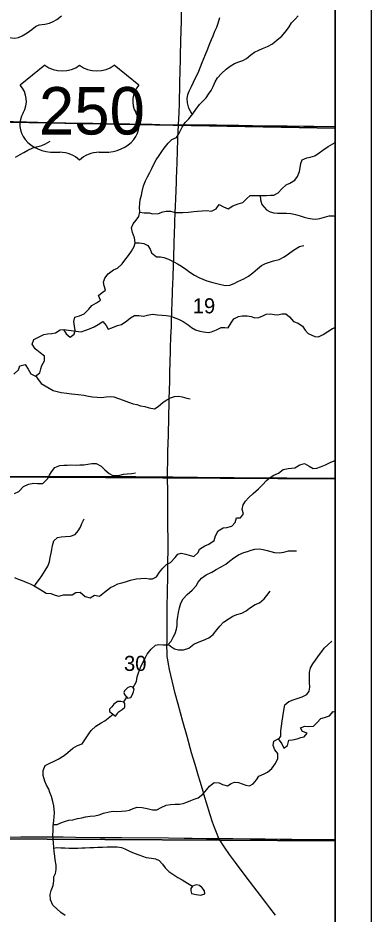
# Model space of a CAD drawing. Extents: x 0 to 34, y 0 to 22.
# Drawn here: x 19.16 to 20.14, y 14.964 to 17.453 of the extents above; entities that cross this region are included whole.
import ezdxf

# ---------------------------------------------------------------- set-up
doc = ezdxf.new("R2010")
doc.units = 0
for name, color, linetype in [('GM_X_County_Road', 7, 'Continuous'), ('GM_X_Minor_Lake', 7, 'Continuous'), ('GM_X_Minor_River', 7, 'Continuous'), ('GM_X_Rail_Line', 7, 'Continuous'), ('GM_X_Section_Text', 7, 'Continuous'), ('GM_X_State_Route', 7, 'Continuous'), ('GM_X_Township_Road', 7, 'Continuous'), ('GM_X_US_Route', 7, 'Continuous'), ('GM_X_US_Shield', 7, 'Continuous'), ('SH_Data', 7, 'Continuous')]:
    doc.layers.add(name, color=color, linetype=linetype)

msp = doc.modelspace()

# ---------------------------------------------------------------- linework, layer by layer
at = {"layer": 'GM_X_County_Road'}
msp.add_lwpolyline([(19.0861, 15.1755), (19.1151, 15.1769), (19.1368, 15.1775), (19.1679, 15.1781), (19.1866, 15.1784), (19.2239, 15.1785), (19.2425, 15.1784), (19.286, 15.1781), (19.3202, 15.1776), (19.3886, 15.1766), (19.4477, 15.1761), (19.5782, 15.1751), (19.6217, 15.1747), (19.6435, 15.1744), (19.6838, 15.1737), (19.718, 15.1739)], dxfattribs=at)
at = {"layer": 'GM_X_Minor_Lake'}
for points in [[(19.4645, 15.5631), (19.4732, 15.565), (19.4778, 15.5715), (19.4812, 15.581), (19.4827, 15.589), (19.4796, 15.5939), (19.4731, 15.5962), (19.4641, 15.5923), (19.4557, 15.5843), (19.4542, 15.579), (19.4558, 15.5733)], [(19.4558, 15.5733), (19.4645, 15.5631)], [(19.4313, 15.5137), (19.4366, 15.5213), (19.4388, 15.5251), (19.4494, 15.5316), (19.457, 15.5384), (19.4574, 15.5487), (19.4539, 15.5528), (19.4456, 15.5547), (19.4365, 15.5539), (19.4266, 15.5471), (19.4206, 15.5398), (19.4149, 15.5334), (19.4142, 15.5269)], [(19.4142, 15.5269), (19.4313, 15.5137)], [(19.6402, 15.0344), (19.6402, 15.0279), (19.6425, 15.0207), (19.6546, 15.0181), (19.6683, 15.0159), (19.6789, 15.0201), (19.6781, 15.0281), (19.6717, 15.0368), (19.664, 15.0428), (19.6561, 15.0447), (19.6493, 15.0435), (19.6451, 15.0412)], [(19.6451, 15.0412), (19.6402, 15.0344)]]:
    msp.add_lwpolyline(points, dxfattribs=at)
at = {"layer": 'GM_X_Minor_River'}
for points in [[(19.0144, 17.4536), (19.0243, 17.4433), (19.0379, 17.4404), (19.055, 17.4362), (19.0687, 17.4332), (19.082, 17.4276), (19.0953, 17.4204), (19.109, 17.4095), (19.12, 17.4046), (19.134, 17.3993), (19.1515, 17.3971), (19.1621, 17.3994), (19.172, 17.4036), (19.1863, 17.412), (19.1988, 17.4211), (19.2091, 17.4295), (19.2197, 17.4341), (19.2348, 17.4357), (19.2481, 17.4387), (19.2583, 17.4437), (19.2682, 17.449), (19.281, 17.4589)], [(19.287, 16.5882), (19.2943, 16.576), (19.3057, 16.5662), (19.3166, 16.5746), (19.3189, 16.5852), (19.3173, 16.5974), (19.3158, 16.6103), (19.318, 16.6224), (19.3313, 16.6259), (19.3445, 16.6316), (19.3574, 16.6441), (19.3653, 16.6544), (19.3786, 16.6617), (19.3892, 16.6689), (19.3835, 16.6818), (19.3937, 16.6909), (19.4035, 16.6967), (19.4001, 16.7092), (19.3982, 16.719), (19.4019, 16.73), (19.411, 16.7426), (19.4254, 16.7533), (19.4367, 16.7586), (19.45, 16.7704), (19.4598, 16.7841), (19.4674, 16.7936), (19.4753, 16.805), (19.4828, 16.8183), (19.4855, 16.8286), (19.4839, 16.8426), (19.4782, 16.857), (19.4751, 16.8703), (19.48, 16.8817), (19.4883, 16.8919), (19.4959, 16.9018), (19.4985, 16.9151), (19.4981, 16.9265), (19.4988, 16.9379), (19.4995, 16.9478), (19.5029, 16.961), (19.5055, 16.9709), (19.5085, 16.9865), (19.5145, 17.0009), (19.5202, 17.0116), (19.5262, 17.0241), (19.5319, 17.0347), (19.5379, 17.0473), (19.5443, 17.0594), (19.5526, 17.0712), (19.5594, 17.0819), (19.5662, 17.0914), (19.5772, 17.1055), (19.587, 17.1157), (19.6003, 17.1215), (19.6071, 17.1317), (19.6165, 17.1503), (19.6244, 17.1625), (19.6347, 17.1732), (19.646, 17.1872), (19.6543, 17.1994), (19.6645, 17.2127), (19.6736, 17.2222), (19.6823, 17.2317), (19.6895, 17.2413), (19.697, 17.2519), (19.7019, 17.2625), (19.7076, 17.2755), (19.714, 17.2865), (19.725, 17.2987), (19.7378, 17.3112), (19.7492, 17.3196), (19.7617, 17.3272), (19.7734, 17.3311), (19.7848, 17.3353), (19.7946, 17.3406), (19.8071, 17.3513), (19.817, 17.3581), (19.8287, 17.3642), (19.8389, 17.3688), (19.8533, 17.3738), (19.867, 17.3818), (19.8802, 17.3925), (19.8931, 17.4031), (19.9055, 17.4184), (19.9135, 17.4286), (19.9199, 17.4393), (19.9297, 17.4495), (19.9384, 17.4591)], [(19.6445, 17.1854), (19.6399, 17.1922), (19.6346, 17.2031), (19.6311, 17.2172), (19.6299, 17.2286), (19.6322, 17.2407), (19.6356, 17.2502), (19.6416, 17.2627), (19.6473, 17.2749), (19.6525, 17.2848), (19.6574, 17.2954), (19.662, 17.3053), (19.6669, 17.3175), (19.6721, 17.33), (19.6763, 17.341), (19.6812, 17.3516), (19.6872, 17.3672), (19.6913, 17.3779), (19.6974, 17.3931), (19.7019, 17.4037), (19.7068, 17.4162), (19.7121, 17.4276), (19.7162, 17.4386), (19.7203, 17.455)], [(19.154, 17.0662), (19.1661, 17.0735), (19.1767, 17.0796), (19.1877, 17.0864), (19.2021, 17.0922), (19.2123, 17.0952), (19.2263, 17.0991), (19.2369, 17.1033), (19.2502, 17.1113)], [(19.4982, 16.9137), (19.5106, 16.9117), (19.5243, 16.9122), (19.5349, 16.9092), (19.5501, 16.91), (19.5622, 16.9146), (19.5721, 16.9161), (19.5834, 16.9161), (19.5967, 16.9131), (19.6074, 16.9124), (19.6176, 16.9128), (19.6339, 16.9136), (19.6487, 16.916), (19.6589, 16.9167), (19.6718, 16.9175), (19.6836, 16.918), (19.6972, 16.9169), (19.7101, 16.923), (19.7192, 16.9351), (19.7306, 16.9287), (19.7439, 16.9231), (19.7571, 16.9318), (19.7715, 16.9368), (19.7848, 16.9407), (19.7943, 16.9509), (19.8045, 16.9597), (19.8151, 16.9601), (19.8504, 16.9602), (19.861, 16.9606), (19.8709, 16.9614), (19.883, 16.9671), (19.8932, 16.9789), (19.9049, 16.99), (19.9148, 16.9946), (19.9288, 17.0029), (19.9363, 17.0125), (19.9416, 17.0269), (19.9435, 17.0371), (19.9453, 17.0489), (19.9491, 17.0595), (19.962, 17.0649), (19.9718, 17.0661), (19.9843, 17.0707), (19.9968, 17.0783), (20.0067, 17.0859), (20.0218, 17.0958), (20.0339, 17.1038), (20.0404, 17.1077)], [(19.8325, 16.9602), (19.8333, 16.948), (19.8372, 16.9355), (19.8501, 16.92), (19.86, 16.9143), (19.8706, 16.9121), (19.8809, 16.911), (19.8949, 16.911), (19.9059, 16.9114), (19.918, 16.9103), (19.9306, 16.9073), (19.9439, 16.9036), (19.9549, 16.9002), (19.9655, 16.8968), (19.9769, 16.8953), (19.9867, 16.8942), (19.9985, 16.8962), (20.0114, 16.9), (20.0243, 16.9031), (20.036, 16.9031), (20.0404, 16.902)], [(19.4855, 16.8286), (19.4968, 16.8282), (19.5094, 16.8271), (19.5208, 16.8215), (19.5276, 16.8112), (19.5307, 16.8006), (19.5447, 16.79), (19.5558, 16.7893), (19.5652, 16.7875), (19.5782, 16.7829), (19.5926, 16.7762), (19.6036, 16.7705), (19.6146, 16.7637), (19.626, 16.7558), (19.6374, 16.7471), (19.6504, 16.7388), (19.6625, 16.7327), (19.6735, 16.7275), (19.6849, 16.7229), (19.7009, 16.7184), (19.7123, 16.7154), (19.7233, 16.7132), (19.7365, 16.7102), (19.7483, 16.7114), (19.7608, 16.7156), (19.771, 16.7209), (19.7877, 16.7286), (19.7998, 16.7358), (19.8123, 16.745), (19.8252, 16.7564), (19.8365, 16.7659), (19.8475, 16.7712), (19.8581, 16.7751), (19.8695, 16.7785), (19.885, 16.7824), (19.899, 16.7892), (19.9112, 16.7976), (19.9248, 16.8083), (19.9414, 16.8182), (19.954, 16.8209)], [(19.287, 16.5882), (19.336, 16.5815), (19.3458, 16.5849), (19.3591, 16.5895), (19.3723, 16.5949), (19.3833, 16.6021), (19.3958, 16.6101), (19.4053, 16.5991), (19.4103, 16.5885), (19.4209, 16.5927), (19.4364, 16.5992), (19.4478, 16.6012), (19.4622, 16.6115), (19.4724, 16.6206), (19.4834, 16.6263), (19.4955, 16.6264), (19.5088, 16.6249), (19.5232, 16.6283), (19.535, 16.6307), (19.5479, 16.6288), (19.5608, 16.6277), (19.5714, 16.6266), (19.5843, 16.6244), (19.5961, 16.6206), (19.606, 16.6161), (19.6192, 16.6104), (19.6329, 16.601), (19.6424, 16.5934), (19.6531, 16.587), (19.6656, 16.5829), (19.6755, 16.5814), (19.6884, 16.5799), (19.6979, 16.5811), (19.7111, 16.5864), (19.7244, 16.5929), (19.7342, 16.5929), (19.7437, 16.5926), (19.752, 16.6063), (19.7592, 16.6173), (19.7725, 16.6242), (19.7827, 16.6261), (19.7963, 16.6258), (19.8081, 16.6243), (19.8176, 16.6205), (19.8286, 16.6209), (19.8396, 16.6255), (19.8494, 16.6301), (19.8612, 16.6309), (19.8711, 16.6294), (19.8806, 16.6287), (19.8934, 16.631), (19.9037, 16.6314), (19.9143, 16.6227), (19.925, 16.6098), (19.9379, 16.6057), (19.9504, 16.5974), (19.9573, 16.586), (19.9661, 16.5762), (19.9843, 16.5683), (19.9945, 16.5676), (20.0078, 16.5737), (20.0207, 16.5824), (20.0335, 16.5901), (20.0404, 16.5933)], [(19.1489, 16.464), (19.1618, 16.4755), (19.1656, 16.4865), (19.18, 16.4907), (19.1883, 16.4778), (19.1963, 16.4646), (19.2089, 16.4582), (19.221, 16.4677), (19.224, 16.4783), (19.227, 16.4878), (19.2345, 16.5003), (19.2338, 16.5136), (19.222, 16.5227), (19.2079, 16.5337), (19.1999, 16.5469), (19.204, 16.5602), (19.2196, 16.5678), (19.2324, 16.5736), (19.2423, 16.5755), (19.2544, 16.5763), (19.2647, 16.5786), (19.2775, 16.5866), (19.287, 16.5882)], [(19.2099, 16.4589), (19.215, 16.4513), (19.2252, 16.4381), (19.2355, 16.4309), (19.2473, 16.4245), (19.2583, 16.4185), (19.2689, 16.4158), (19.2807, 16.4132), (19.2959, 16.411), (19.3092, 16.4095), (19.3274, 16.4073), (19.3433, 16.4054), (19.3562, 16.4025), (19.3676, 16.4006), (19.3801, 16.3995), (19.3919, 16.3991), (19.4048, 16.4003), (19.4173, 16.4015), (19.4268, 16.4008), (19.4397, 16.3959), (19.4522, 16.391), (19.467, 16.3857), (19.4803, 16.3812), (19.4906, 16.379), (19.5001, 16.376), (19.5122, 16.3737), (19.5247, 16.3703), (19.5392, 16.3673), (19.5498, 16.3742), (19.5634, 16.386), (19.5732, 16.3925), (19.5842, 16.3982), (19.5952, 16.4013), (19.6058, 16.4021), (19.6157, 16.4006), (19.629, 16.3972), (19.6385, 16.395)], [(19.1507, 16.1324), (19.1624, 16.1374), (19.176, 16.1519), (19.1893, 16.1583), (19.2041, 16.161), (19.2147, 16.1603), (19.2295, 16.16), (19.2423, 16.1725), (19.248, 16.1828), (19.2537, 16.1927), (19.2631, 16.2041), (19.2768, 16.2095), (19.2874, 16.2106), (19.2972, 16.211), (19.3075, 16.2114), (19.3219, 16.2111), (19.3325, 16.2115), (19.3435, 16.2119), (19.3545, 16.2135), (19.3651, 16.2158), (19.3773, 16.2155), (19.3909, 16.2079), (19.4016, 16.1977), (19.4134, 16.1875), (19.4236, 16.1822), (19.4335, 16.1819), (19.4434, 16.1834), (19.4532, 16.1857), (19.4634, 16.1869), (19.4767, 16.1881), (19.487, 16.1892)], [(19.151, 15.8991), (19.1608, 15.8946), (19.1719, 15.8908), (19.1848, 15.8851), (19.1943, 15.881), (19.2053, 15.8757), (19.2193, 15.8674), (19.2288, 15.8614), (19.2391, 15.8557), (19.2516, 15.8546), (19.2634, 15.8493), (19.274, 15.8467), (19.2869, 15.8509), (19.3002, 15.8502), (19.3112, 15.8506), (19.321, 15.8567), (19.3335, 15.8579), (19.3472, 15.8462), (19.3609, 15.8421), (19.3726, 15.8493), (19.3867, 15.8471), (19.4007, 15.8577), (19.417, 15.8714), (19.4276, 15.876), (19.4378, 15.881), (19.4484, 15.8841), (19.4586, 15.8871), (19.4723, 15.8913), (19.4882, 15.8948), (19.5015, 15.8964), (19.514, 15.8968), (19.5242, 15.8953), (19.5341, 15.8953), (19.5447, 15.9003), (19.5534, 15.914), (19.5621, 15.925), (19.5727, 15.9349), (19.584, 15.9406), (19.5965, 15.9539), (19.6041, 15.9635), (19.6136, 15.9665), (19.6261, 15.9639), (19.6382, 15.9598), (19.6489, 15.9575), (19.6606, 15.9682), (19.664, 15.9777), (19.6795, 15.9865), (19.6901, 15.9914), (19.7045, 16.0017), (19.7086, 16.0142), (19.7158, 16.0283), (19.7302, 16.0371), (19.7404, 16.0375), (19.7541, 16.0413), (19.7628, 16.0516), (19.7665, 16.0645), (19.7779, 16.0645), (19.7866, 16.0752), (19.7831, 16.0877), (19.7858, 16.101), (19.7918, 16.1105), (19.8001, 16.1204), (19.8134, 16.1322), (19.8281, 16.1447), (19.8395, 16.1565), (19.8504, 16.1687), (19.8606, 16.1767), (19.8705, 16.1828), (19.8834, 16.1889), (19.8966, 16.1985), (19.9103, 16.2019), (19.9285, 16.2035), (19.9429, 16.2119), (19.9561, 16.2153), (19.969, 16.2085), (19.9793, 16.2017), (19.9903, 16.2029), (20.0005, 16.2064), (20.0138, 16.2121), (20.0267, 16.2186), (20.038, 16.2228), (20.0404, 16.2236)], [(19.2065, 15.875), (19.211, 15.8818), (19.22, 15.894), (19.2268, 15.9035), (19.2363, 15.9179), (19.2431, 15.9301), (19.2476, 15.9419), (19.2494, 15.954), (19.2521, 15.9662), (19.2543, 15.9768), (19.2562, 15.9874), (19.2599, 16.0007), (19.2701, 16.0102), (19.28, 16.0118), (19.2925, 16.013), (19.3062, 16.0134), (19.319, 16.0184), (19.3277, 16.0282), (19.3338, 16.0389), (19.3375, 16.0488), (19.3439, 16.0617)], [(19.4799, 15.5933), (19.489, 15.6102), (19.4917, 15.6228), (19.495, 15.6342), (19.5003, 15.649), (19.506, 15.6608), (19.5135, 15.6748), (19.5192, 15.6855), (19.5297, 15.6995), (19.5419, 15.7106), (19.5517, 15.7129), (19.5627, 15.7118), (19.576, 15.7118), (19.5858, 15.7221), (19.5915, 15.7331), (19.5971, 15.7434), (19.6005, 15.7555), (19.602, 15.765), (19.6027, 15.7775), (19.6038, 15.7904), (19.6061, 15.8018), (19.6091, 15.8144), (19.6124, 15.8273), (19.6185, 15.8398), (19.6298, 15.8516), (19.6438, 15.8638), (19.6548, 15.8752), (19.6608, 15.8858), (19.6695, 15.8969), (19.6828, 15.9064), (19.6987, 15.914), (19.7108, 15.9213), (19.7244, 15.9282), (19.7373, 15.9362), (19.7475, 15.9445), (19.7593, 15.9533), (19.7725, 15.9621), (19.7873, 15.9678), (19.7979, 15.9713), (19.8074, 15.9747), (19.818, 15.9778), (19.8305, 15.9782), (19.8411, 15.9767), (19.8521, 15.9741), (19.8624, 15.9707), (19.8723, 15.9681), (19.8852, 15.967), (19.898, 15.9689), (19.9117, 15.9724), (19.9231, 15.9732), (19.9337, 15.9728)], [(19.5777, 15.7136), (19.5836, 15.708), (19.5946, 15.7005), (19.6064, 15.6975), (19.6197, 15.6979), (19.6344, 15.7029), (19.6481, 15.7132), (19.659, 15.7185), (19.6753, 15.7246), (19.6897, 15.7315), (19.7022, 15.7403), (19.7128, 15.7536), (19.7207, 15.7635), (19.7309, 15.7749), (19.7465, 15.7852), (19.7567, 15.7909), (19.7681, 15.7963), (19.7813, 15.7993), (19.7934, 15.8066), (19.8033, 15.8134), (19.8192, 15.8234), (19.8306, 15.8287), (19.8434, 15.8394), (19.851, 15.8492), (19.8608, 15.8607)], [(19.8839, 15.449), (19.8901, 15.4582), (19.89, 15.4726), (19.8915, 15.4855), (19.8941, 15.4999), (19.8956, 15.5121), (19.8993, 15.5349), (19.9012, 15.5451), (19.9125, 15.5543), (19.9239, 15.5592), (19.9383, 15.5631), (19.9493, 15.5673), (19.9618, 15.5734), (19.969, 15.5829), (19.9701, 15.5939), (19.9693, 15.6072), (19.9692, 15.6193), (19.9696, 15.6345), (19.9722, 15.6482), (19.9786, 15.6588), (19.9866, 15.6691), (19.9945, 15.6808), (20.0036, 15.693), (20.0103, 15.7029), (20.0213, 15.7128), (20.0312, 15.7223)], [(19.4619, 15.5661), (19.4532, 15.553)], [(19.266, 15.0993), (19.264, 15.114), (19.2625, 15.125), (19.2609, 15.1379), (19.2598, 15.1489), (19.2586, 15.1618), (19.2578, 15.1717), (19.2574, 15.1827), (19.2577, 15.1952), (19.2584, 15.2085), (19.2599, 15.2229), (19.261, 15.2343), (19.2614, 15.2453), (19.2602, 15.2643), (19.2575, 15.2764), (19.2537, 15.2901), (19.2491, 15.3014), (19.2464, 15.3109), (19.2399, 15.3219), (19.2353, 15.3329), (19.2303, 15.3488), (19.2307, 15.3628), (19.2356, 15.3761), (19.2484, 15.3834), (19.2594, 15.388), (19.2716, 15.3941), (19.289, 15.4047), (19.2992, 15.4124), (19.3124, 15.4242), (19.3253, 15.4322), (19.3386, 15.4371), (19.348, 15.4508), (19.3571, 15.4641), (19.3639, 15.4736), (19.3767, 15.4855), (19.3915, 15.495), (19.4014, 15.5007), (19.4246, 15.5188)], [(19.2589, 15.2127), (19.2691, 15.2127), (19.2793, 15.2173), (19.2891, 15.2207), (19.3016, 15.2242), (19.3123, 15.2257), (19.3259, 15.2288), (19.3377, 15.2315), (19.3483, 15.2338), (19.3604, 15.2354), (19.3741, 15.2369), (19.3854, 15.2396), (19.3979, 15.2438), (19.4135, 15.2477), (19.4248, 15.2492), (19.4351, 15.2489), (19.4476, 15.2493), (19.4594, 15.2501), (19.4696, 15.2528), (19.4806, 15.2574), (19.4912, 15.2604), (19.5049, 15.2597), (19.5193, 15.2567), (19.5337, 15.2534), (19.5462, 15.253), (19.5583, 15.2599), (19.5716, 15.266), (19.5841, 15.2683), (19.597, 15.2687), (19.6088, 15.2695), (19.6186, 15.2711), (19.6289, 15.2749), (19.6398, 15.2791), (19.6497, 15.2833), (19.6607, 15.2871), (19.6739, 15.297), (19.6845, 15.31), (19.6917, 15.3195), (19.7053, 15.3294), (19.7186, 15.3287), (19.7281, 15.3238), (19.7418, 15.3204), (19.752, 15.3265), (19.7618, 15.3303), (19.7728, 15.3288), (19.7831, 15.3255), (19.793, 15.3217), (19.8028, 15.3198), (19.8134, 15.3259), (19.8221, 15.3362), (19.8293, 15.3465), (19.8433, 15.353), (19.8532, 15.3583), (19.8649, 15.3678), (19.8747, 15.3815), (19.8815, 15.3952), (19.8815, 15.4096), (19.8731, 15.4198), (19.8689, 15.4316), (19.8704, 15.4445), (19.8825, 15.451), (19.8924, 15.437), (19.8981, 15.4245), (19.9083, 15.4321), (19.9121, 15.4469), (19.922, 15.4477), (19.9352, 15.4504), (19.9451, 15.4546), (19.9549, 15.4557), (19.9632, 15.466), (19.9503, 15.4705), (19.945, 15.4811), (19.9564, 15.4853), (19.9681, 15.4846), (19.9803, 15.4862), (19.9901, 15.4953), (20.0011, 15.5075), (20.0113, 15.5098), (20.0246, 15.5144), (20.0351, 15.5266), (20.0404, 15.5253)], [(19.2599, 15.1472), (19.2681, 15.149), (19.2791, 15.1479), (19.2905, 15.1475), (19.3026, 15.1468), (19.3265, 15.1469), (19.3375, 15.1473), (19.347, 15.1481), (19.3599, 15.1485), (19.3709, 15.1485), (19.3823, 15.1493), (19.3952, 15.1497), (19.4084, 15.1502), (19.4191, 15.1506), (19.4358, 15.1502), (19.4475, 15.1484), (19.457, 15.145), (19.4696, 15.1382), (19.4828, 15.1329), (19.4958, 15.1284), (19.5163, 15.1213), (19.5307, 15.1187), (19.5417, 15.1168), (19.5519, 15.113), (19.5615, 15.1021), (19.5691, 15.0922), (19.5793, 15.0824), (19.5926, 15.0729), (19.6044, 15.0654), (19.6162, 15.059), (19.6314, 15.0499), (19.6451, 15.0412)], [(19.2914, 14.9597), (19.2792, 14.9684), (19.2686, 14.9779), (19.2576, 14.9884), (19.2503, 15.0036), (19.2499, 15.0184), (19.2529, 15.029), (19.2585, 15.0427), (19.2604, 15.0556), (19.26, 15.067), (19.2649, 15.0765), (19.2664, 15.0875), (19.266, 15.0993)]]:
    msp.add_lwpolyline(points, dxfattribs=at)
at = {"layer": 'GM_X_Rail_Line'}
msp.add_lwpolyline([(20.0404, 14.169), (20.0404, 20.2202), (19.5489, 20.2208), (19.5137, 20.2208), (19.105, 20.2214), (19.1046, 20.1073), (19.1032, 19.1112), (19.0976, 18.2716), (19.0975, 18.2511), (19.0972, 18.1277), (19.0934, 17.1717), (19.0896, 16.1806), (19.0858, 15.176), (19.082, 14.1642)], close=True, dxfattribs=at)
at = {"layer": 'GM_X_State_Route'}
for points in [[(19.6061, 17.1568), (19.6074, 17.1902), (19.6084, 17.215), (19.6099, 17.271), (19.6107, 17.3082), (19.6113, 17.3362), (19.6117, 17.3517), (19.6127, 17.3859), (19.6135, 17.4201), (19.6139, 17.4419), (19.6145, 17.4698)], [(19.6005, 17.0097), (19.6011, 17.0257), (19.6028, 17.0814), (19.6042, 17.1186), (19.6061, 17.1568)], [(19.5955, 16.8802), (19.5957, 16.8864), (19.5969, 16.9142), (19.5975, 16.9297), (19.5982, 16.9514), (19.5991, 16.973), (19.6001, 16.9978), (19.6005, 17.0097)], [(19.5889, 16.6884), (19.589, 16.6894), (19.5892, 16.6975), (19.5898, 16.713), (19.5907, 16.7346), (19.5917, 16.7656), (19.5926, 16.7904), (19.5937, 16.8245), (19.5947, 16.8585), (19.5954, 16.8771), (19.5955, 16.8802)], [(19.584, 16.537), (19.5851, 16.5663), (19.5863, 16.5972), (19.5869, 16.6127), (19.5889, 16.6884)], [(19.8748, 14.9609), (19.8598, 14.9807), (19.8485, 14.9955), (19.8335, 15.0152), (19.8241, 15.0275), (19.7942, 15.0671), (19.7644, 15.1068), (19.7479, 15.1293), (19.7336, 15.1496), (19.718, 15.1739), (19.7112, 15.1901), (19.7056, 15.2045), (19.7004, 15.2192), (19.6937, 15.2398), (19.6837, 15.2723), (19.6792, 15.2872), (19.6722, 15.311), (19.666, 15.3318), (19.6618, 15.3467), (19.6518, 15.3792), (19.6464, 15.397), (19.642, 15.4119), (19.6299, 15.4568), (19.6179, 15.4986), (19.6048, 15.5465), (19.5971, 15.5766), (19.5811, 15.6429), (19.5779, 15.6581), (19.5759, 15.6703), (19.5748, 15.6795), (19.5741, 15.6918), (19.5739, 15.7073), (19.5742, 15.7228), (19.5743, 15.7383), (19.5743, 15.76), (19.5742, 15.791), (19.5747, 15.8189), (19.5756, 15.8561), (19.5758, 15.8728), (19.5759, 15.8881), (19.576, 15.9087), (19.5761, 15.9243), (19.5764, 15.9367), (19.5767, 15.9522), (19.5769, 15.9646), (19.5771, 15.9863), (19.577, 16.008), (19.5767, 16.039), (19.5764, 16.07), (19.5762, 16.0979), (19.576, 16.1445), (19.5757, 16.1693), (19.5757, 16.1782), (19.5757, 16.191), (19.5762, 16.2252), (19.5766, 16.25), (19.5778, 16.2935), (19.5783, 16.309), (19.5788, 16.3306), (19.5792, 16.3523), (19.58, 16.3771), (19.5805, 16.3988), (19.5809, 16.4144), (19.5817, 16.4484), (19.582, 16.4639), (19.5829, 16.5012), (19.5835, 16.5229), (19.584, 16.537)]]:
    msp.add_lwpolyline(points, dxfattribs=at)
at = {"layer": 'GM_X_Township_Road'}
for points in [[(19.0898, 16.1801), (19.103, 16.18), (19.1278, 16.1797), (19.1649, 16.1796), (19.1897, 16.1796), (19.2115, 16.1796), (19.2581, 16.1797), (19.2798, 16.1796), (19.2984, 16.1796), (19.3294, 16.1796), (19.376, 16.1793), (19.4599, 16.1791), (19.4878, 16.179), (19.5312, 16.1788), (19.5529, 16.1785), (19.5757, 16.1782)], [(19.5757, 16.1782), (19.5902, 16.178), (19.6585, 16.1771), (19.7206, 16.1766), (19.7361, 16.1765), (19.7609, 16.1762), (19.7858, 16.1759), (19.823, 16.1757), (19.8448, 16.1757), (19.8603, 16.1758), (19.8789, 16.1759), (19.9067, 16.1756), (19.9222, 16.1752), (19.9594, 16.1749), (20.006, 16.1748), (20.0404, 16.1747)], [(19.718, 15.1739), (19.7566, 15.1735), (19.8062, 15.1727), (19.8465, 15.1723), (19.8869, 15.1721), (19.9209, 15.1714), (19.9395, 15.171), (19.9642, 15.1712), (19.9983, 15.1708), (20.0385, 15.171), (20.0404, 15.171)]]:
    msp.add_lwpolyline(points, dxfattribs=at)
at = {"layer": 'GM_X_US_Route'}
for points in [[(19.0936, 17.1712), (19.0947, 17.171), (19.1132, 17.1684), (19.1286, 17.1669), (19.1472, 17.1659), (19.1845, 17.1646), (19.2466, 17.1627), (19.2932, 17.1618), (19.3678, 17.1608), (19.3927, 17.1603), (19.4238, 17.1596), (19.4704, 17.1591), (19.5077, 17.1583), (19.5326, 17.1579), (19.5543, 17.1576), (19.6061, 17.1568)], [(19.6061, 17.1568), (19.6246, 17.1571), (19.6464, 17.1567), (19.7116, 17.156), (19.7737, 17.1552), (19.8109, 17.1548), (19.8886, 17.1538), (19.9072, 17.1536), (19.9538, 17.153), (19.9818, 17.1526), (20.0404, 17.1516)]]:
    msp.add_lwpolyline(points, dxfattribs=at)
at = {"layer": 'GM_X_US_Shield'}
for p, q in [((19.2351, 17.3218), (19.1665, 17.2668)), ((19.496, 17.2668), (19.4274, 17.3218)), ((19.2626, 17.0801), (19.2763, 17.0801)), ((19.3862, 17.0801), (19.3999, 17.0801))]:
    msp.add_line(p, q, dxfattribs=at)
for points in [[(20.0404, 17.1473), (20.0404, 18.1586), (19.0961, 18.167), (19.0893, 17.1816), (19.0897, 17.1649)], [(20.0404, 16.173), (20.0404, 17.1473), (19.0897, 17.1649), (19.0829, 16.1788)], [(20.0404, 15.1674), (20.0404, 16.173), (19.0829, 16.1788), (19.0804, 15.1729)], [(20.0404, 14.1653), (20.0404, 15.1674), (19.0804, 15.1729), (19.0847, 14.1682)]]:
    msp.add_lwpolyline(points, close=True, dxfattribs=at)
for centre, major_axis, start_param, end_param in [((19.2832, 17.361), (-0.0687, 0), 0.795399, 2.346194), ((19.3793, 17.361), (-0.0687, 0), 0.795399, 2.346194), ((19.0877, 17.2227), (0.0961, 0), 5.838949, 6.894067), ((19.5748, 17.2227), (-0.0961, 0), 5.672304, 6.727422), ((19.2615, 17.157), (0.0961, 0), 2.702327, 4.723529), ((19.401, 17.157), (-0.0961, 0), 1.559657, 3.580859), ((19.2763, 17.0251), (-0.0687, 0), 3.785094, 4.712389), ((19.3862, 17.0251), (-0.0687, 0), 4.712389, 5.639684)]:
    msp.add_ellipse(centre, major_axis=major_axis, ratio=0.8, start_param=start_param, end_param=end_param, dxfattribs=at)
at = {"layer": 'SH_Data'}
for p, q in [((20.1404, 21), (20.1404, 14)), ((20.0404, 20.9), (20.0404, 14.1))]:
    msp.add_line(p, q, dxfattribs=at)

# ---------------------------------------------------------------- texts
at = {"layer": 'GM_X_Section_Text'}
for s, p in [('19', (19.6455, 16.6326)), ('30', (19.4547, 15.6392))]:
    msp.add_text(s, height=0.04186, rotation=0, dxfattribs=at).set_placement(p)
at = {"layer": 'GM_X_US_Shield'}
msp.add_text('250', height=0.13184, dxfattribs=at).set_placement((19.2185, 17.1295))

doc.saveas('drawing.dxf')
